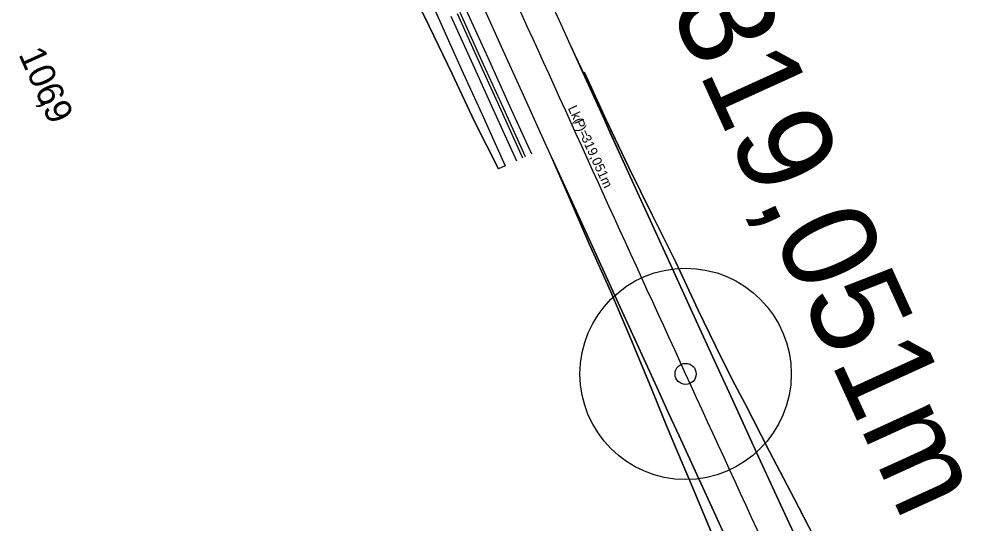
# Model space of a CAD drawing. Extents: x -678487 to -674601, y -1104811 to -1093295.
# Drawn here: x -675341.3 to -675158.8, y -1103490.7 to -1103395.2 of the extents above; entities that cross this region are included whole.
import ezdxf

# ---------------------------------------------------------------- set-up
doc = ezdxf.new("R2010")
doc.units = 0
for name, color, linetype in [('SOxxxxxx_Koleje_param další_Popis', 7, 'Continuous'), ('SOxxxxxx_Koleje_param další_Popis10', 7, 'Continuous'), ('SOxxxxxx_Osa_bod_P', 7, 'Continuous'), ('SOxxxxxx_Staničení_Popis', 7, 'Continuous'), ('SOxxxxxx_Staničení_Popis10', 7, 'Continuous'), ('SOxxxxxx_ŽSp_hrana', 7, 'Continuous'), ('SOxxxxxx_ŽSp_násyp_hrana', 7, 'Continuous'), ('SOxxxxxx_ŽSp_násyp_plocha', 7, 'Continuous'), ('SOxxxxxx_ŽSp_odvodnění', 7, 'Continuous'), ('SOxxxxxx_ŽSp_zářez_hrana', 7, 'Continuous'), ('SOxxxxxx_ŽSp_zářez_plocha', 7, 'Continuous')]:
    doc.layers.add(name, color=color, linetype=linetype)

msp = doc.modelspace()

# ---------------------------------------------------------------- linework, layer by layer
at = {"layer": 'SOxxxxxx_Osa_bod_P'}
msp.add_open_spline([(-675299.82, -1103273.48), (-675289.22, -1103297.86), (-675267.77, -1103346.52), (-675234.89, -1103419.19), (-675201.67, -1103491.71), (-675179.34, -1103539.96), (-675168.18, -1103564.1)], degree=3, dxfattribs=at)
at = {"layer": 'SOxxxxxx_Staničení_Popis'}
msp.add_line((-675215.1, -1103462.32), (-675215.1, -1103462.32), dxfattribs=at)
msp.add_circle((-675215.1, -1103462.32), 2, dxfattribs=at)
at = {"layer": 'SOxxxxxx_Staničení_Popis10'}
msp.add_line((-675215.1, -1103462.32), (-675215.1, -1103462.32), dxfattribs=at)
msp.add_circle((-675215.1, -1103462.32), 20, dxfattribs=at)
at = {"layer": 'SOxxxxxx_ŽSp_hrana'}
for points in [[(-675192.93, -1103496.15), (-675197.12, -1103487.07), (-675201.29, -1103477.99), (-675205.47, -1103468.9), (-675207.25, -1103465.01), (-675209.64, -1103459.82), (-675213.8, -1103450.73), (-675217.97, -1103441.64), (-675222.12, -1103432.55), (-675226.27, -1103423.45), (-675229.36, -1103416.67), (-675230.41, -1103414.36), (-675234.55, -1103405.26), (-675238.68, -1103396.16), (-675242.8, -1103387.05)], [(-675208.03, -1103492.1), (-675212.21, -1103483.01), (-675216.39, -1103473.92), (-675218.18, -1103470.03), (-675220.56, -1103464.83), (-675224.73, -1103455.74), (-675228.9, -1103446.64), (-675233.05, -1103437.54), (-675237.21, -1103428.44), (-675240.3, -1103421.65), (-675241.35, -1103419.34), (-675245.49, -1103410.23), (-675249.63, -1103401.12), (-675253.75, -1103392)]]:
    msp.add_lwpolyline(points, dxfattribs=at)
at = {"layer": 'SOxxxxxx_ŽSp_násyp_hrana'}
for p, q in [((-675234.3, -1103405.15), (-675230.16, -1103414.24)), ((-675230.16, -1103414.24), (-675229.05, -1103416.53)), ((-675229.05, -1103416.53), (-675225.83, -1103423.25)), ((-675240.31, -1103421.65), (-675237.35, -1103428.5)), ((-675225.83, -1103423.25), (-675221.46, -1103432.24)), ((-675237.35, -1103428.5), (-675233.34, -1103437.67)), ((-675221.46, -1103432.24), (-675216.94, -1103441.17)), ((-675233.34, -1103437.67), (-675229.25, -1103446.8)), ((-675216.94, -1103441.17), (-675212.72, -1103450.23)), ((-675229.25, -1103446.8), (-675225.32, -1103456.01)), ((-675212.72, -1103450.23), (-675208.37, -1103459.24)), ((-675225.32, -1103456.01), (-675221.49, -1103465.25)), ((-675208.37, -1103459.24), (-675205.77, -1103464.33)), ((-675205.77, -1103464.33), (-675203.77, -1103468.12)), ((-675221.49, -1103465.25), (-675219.34, -1103470.56)), ((-675203.77, -1103468.12), (-675199.19, -1103477.02)), ((-675219.34, -1103470.56), (-675217.72, -1103474.53)), ((-675217.72, -1103474.53), (-675213.82, -1103483.75)), ((-675199.19, -1103477.02), (-675194.54, -1103485.88)), ((-675213.82, -1103483.75), (-675209.96, -1103492.98)), ((-675194.54, -1103485.88), (-675189.96, -1103494.78))]:
    msp.add_line(p, q, dxfattribs=at)
at = {"layer": 'SOxxxxxx_ŽSp_násyp_plocha'}
for points in [[(-675236.7, -1103400.56), (-675226.27, -1103423.45), (-675222.12, -1103432.55), (-675217.97, -1103441.64), (-675213.8, -1103450.73), (-675209.64, -1103459.82), (-675207.25, -1103465.01), (-675205.47, -1103468.9), (-675201.29, -1103477.99), (-675197.12, -1103487.07), (-675192.93, -1103496.15), (-675188.75, -1103505.23), (-675185.02, -1103513.31), (-675184.56, -1103514.31), (-675180.37, -1103523.39), (-675176.18, -1103532.47), (-675171.99, -1103541.54), (-675167.79, -1103550.62), (-675162.73, -1103561.58), (-675104.87, -1103686.78)], [(-675189.96, -1103494.78), (-675194.54, -1103485.88), (-675199.19, -1103477.02), (-675203.77, -1103468.12), (-675205.77, -1103464.33), (-675208.37, -1103459.24), (-675212.72, -1103450.23), (-675216.94, -1103441.17), (-675221.46, -1103432.24), (-675225.83, -1103423.25), (-675236.7, -1103400.56)], [(-675240.47, -1103421.28), (-675237.21, -1103428.44), (-675233.05, -1103437.54), (-675228.9, -1103446.64), (-675224.73, -1103455.74), (-675220.56, -1103464.83), (-675218.18, -1103470.03), (-675216.39, -1103473.92), (-675212.21, -1103483.01), (-675208.03, -1103492.1), (-675203.85, -1103501.18), (-675199.66, -1103510.26), (-675195.94, -1103518.34), (-675195.47, -1103519.35), (-675191.28, -1103528.43), (-675187.09, -1103537.51), (-675182.9, -1103546.59), (-675178.7, -1103555.66), (-675173.64, -1103566.62), (-675115.78, -1103691.83)], [(-675209.96, -1103492.98), (-675213.82, -1103483.75), (-675217.72, -1103474.53), (-675219.34, -1103470.56), (-675221.49, -1103465.25), (-675225.32, -1103456.01), (-675229.25, -1103446.8), (-675233.34, -1103437.67), (-675237.35, -1103428.5), (-675240.47, -1103421.28)]]:
    msp.add_lwpolyline(points, dxfattribs=at)
at = {"layer": 'SOxxxxxx_ŽSp_odvodnění'}
for p, q in [((-675258.35, -1103394.08), (-675254.23, -1103403.2)), ((-675257.85, -1103393.86), (-675253.73, -1103402.97)), ((-675254.23, -1103403.2), (-675250.09, -1103412.32)), ((-675253.73, -1103402.97), (-675249.59, -1103412.09)), ((-675250.09, -1103412.32), (-675245.95, -1103421.43)), ((-675249.59, -1103412.09), (-675245.45, -1103421.2))]:
    msp.add_line(p, q, dxfattribs=at)
at = {"layer": 'SOxxxxxx_ŽSp_zářez_hrana'}
for p, q in [((-675268.07, -1103387.48), (-675263.65, -1103396.48)), ((-675265.76, -1103386.44), (-675261.63, -1103395.57)), ((-675256.69, -1103393.33), (-675252.56, -1103402.45)), ((-675259.52, -1103394.61), (-675255.39, -1103403.73)), ((-675263.65, -1103396.48), (-675259.3, -1103405.5)), ((-675261.63, -1103395.57), (-675257.51, -1103404.69)), ((-675252.56, -1103402.45), (-675248.43, -1103411.56)), ((-675255.39, -1103403.73), (-675251.26, -1103412.84)), ((-675259.3, -1103405.5), (-675255.06, -1103414.57)), ((-675257.51, -1103404.69), (-675253.37, -1103413.8)), ((-675248.43, -1103411.56), (-675244.28, -1103420.67)), ((-675251.26, -1103412.84), (-675247.12, -1103421.96)), ((-675255.06, -1103414.57), (-675250.52, -1103423.5)), ((-675253.37, -1103413.8), (-675249.23, -1103422.92))]:
    msp.add_line(p, q, dxfattribs=at)
at = {"layer": 'SOxxxxxx_ŽSp_zářez_plocha'}
msp.add_line((-675249.23, -1103422.92), (-675250.52, -1103423.5), dxfattribs=at)
for points in [[(-675313.26, -1103279.32), (-675310.47, -1103285.74), (-675306.46, -1103294.92), (-675302.44, -1103304.1), (-675298.4, -1103313.27), (-675294.36, -1103322.43), (-675291.85, -1103328.1), (-675290.3, -1103331.59), (-675286.23, -1103340.74), (-675282.16, -1103349.89), (-675278.07, -1103359.04), (-675273.97, -1103368.18), (-675270.13, -1103376.73), (-675269.87, -1103377.31), (-675265.76, -1103386.44), (-675261.63, -1103395.57), (-675257.51, -1103404.69), (-675253.37, -1103413.8), (-675249.23, -1103422.92)], [(-675250.52, -1103423.5), (-675255.06, -1103414.57), (-675259.3, -1103405.5), (-675263.65, -1103396.48), (-675268.07, -1103387.48)]]:
    msp.add_lwpolyline(points, dxfattribs=at)

# ---------------------------------------------------------------- texts
at = {"layer": 'SOxxxxxx_Koleje_param další_Popis'}
for s, p in [('Lk(', (-675237.43, -1103412.01)), ('P', (-675236.24, -1103414.62)), (')=', (-675235.67, -1103415.87)), ('319,051m', (-675234.89, -1103417.59))]:
    msp.add_text(s, height=1.8, rotation=294.4765, dxfattribs=at).set_placement(p)
at = {"layer": 'SOxxxxxx_Koleje_param další_Popis10'}
msp.add_text('319,051m', height=18, rotation=294.4765, dxfattribs=at).set_placement((-675218.21, -1103393.07))
at = {"layer": 'SOxxxxxx_Staničení_Popis'}
for s, p in [('106', (-675341.46, -1103401.81)), (',', (-675337.54, -1103410.52)), ('9', (-675336.89, -1103411.97))]:
    msp.add_text(s, height=5, rotation=294.2261, dxfattribs=at).set_placement(p)

doc.saveas('drawing.dxf')
